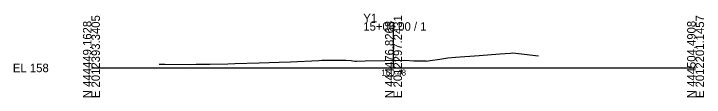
# Model space of a CAD drawing. Extents: x -26 to 3203, y -10 to 9517.
# Drawn here: x 974.3 to 1202.8, y -9.7 to 18 of the extents above; entities that cross this region are included whole.
import ezdxf

# ---------------------------------------------------------------- set-up
doc = ezdxf.new("R2010")
doc.units = 0
for name, color, linetype in [('Default', 7, 'Continuous'), ('Exist Cross Section Cell', 7, 'Continuous'), ('Exist XS Center Line Elevation Label', 7, 'Continuous'), ('Exist XS Ground Line', 7, 'Continuous')]:
    doc.layers.add(name, color=color, linetype=linetype)

msp = doc.modelspace()

# ---------------------------------------------------------------- linework, layer by layer
at = {"layer": 'Exist Cross Section Cell'}
for p, q in [((1100, 0), (1100, 15.16)), ((1000, 0), (1100, 0)), ((1100, 0), (1200, 0))]:
    msp.add_line(p, q, dxfattribs=at)
at = {"layer": 'Exist XS Ground Line'}
msp.add_lwpolyline([(1022.43, 1.28), (1024.29, 1.22), (1032.88, 1.2), (1034.69, 1.24), (1039.17, 1.26), (1045.1, 1.35), (1047.5, 1.43), (1055.51, 1.67), (1062.11, 1.87), (1065.91, 2.03), (1075.32, 2.51), (1076.32, 2.57), (1084.18, 2.59), (1085.94, 2.47), (1086.5, 2.39), (1087.34, 2.29), (1087.71, 2.24), (1090.61, 2.32), (1097.13, 2.5), (1098.65, 2.53), (1099.41, 2.49), (1100, 2.48), (1103.73, 2.56), (1106.7, 2.39), (1107.54, 2.38), (1108.33, 2.35), (1110.72, 2.38), (1110.84, 2.26), (1112.1, 2.44), (1115.3, 2.9), (1117.94, 3.36), (1120.56, 3.56), (1128.35, 4.08), (1135.17, 4.68), (1138.76, 4.96), (1139.53, 5.05), (1148.02, 4.04)], dxfattribs=at)

# ---------------------------------------------------------------- texts
at = {"layer": 'Default'}
msp.add_text('-', height=0.0001, dxfattribs=at).set_placement((1000, 0))
at = {"layer": 'Exist Cross Section Cell'}
for s, p in [('E 2012393.3405', (1002.8, -10)), ('E 2012297.2431', (1102.8, -10)), ('E 2012201.1457', (1202.8, -10)), ('N 444449.1628', (1000, -10)), ('N 444476.8268', (1100, -10)), ('N 444504.4908', (1200, -10))]:
    msp.add_text(s, height=2.8, rotation=90, dxfattribs=at).set_placement(p)
for s, p in [('Y1', (1090, 15.16)), ('15+00.00 / 1', (1090, 12.36)), ('EL 158', (974, -1.4))]:
    msp.add_text(s, height=2.8, dxfattribs=at).set_placement(p)
at = {"layer": 'Exist XS Center Line Elevation Label'}
msp.add_text('160.48', height=2, dxfattribs=at).set_placement((1095.96, -2.52))

doc.saveas('drawing.dxf')
